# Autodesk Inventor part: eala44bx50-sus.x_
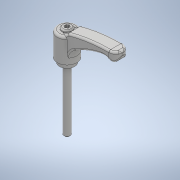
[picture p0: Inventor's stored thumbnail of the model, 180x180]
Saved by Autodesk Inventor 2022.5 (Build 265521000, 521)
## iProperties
Created: 2018-05
Part Number: eala44bx50-sus.x_
Material: 一般
Document SubType Name: Modeling
Designer: imaocorp
Density: 1 g/cm^3
Appearance: 既定
Sending System: SOLIDWORKS 2016-2016286
MC: AMD64
MC_MODEL: AMD64 Family 21 Model 2 Stepping 0, AuthenticAMD
OS: Windows_NT
FRU: Parasolid Version 28.0, build 224,  7-29-2016
FORMAT: text
GUISE: transmit
KEY: eala44bx50-sus
FILE: eala44bx50-sus.x_t
DATE: Fri May 18 11:28:36 2018
Author: imaocorp
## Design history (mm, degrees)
feature "Base1"
node "ソリッド1"
